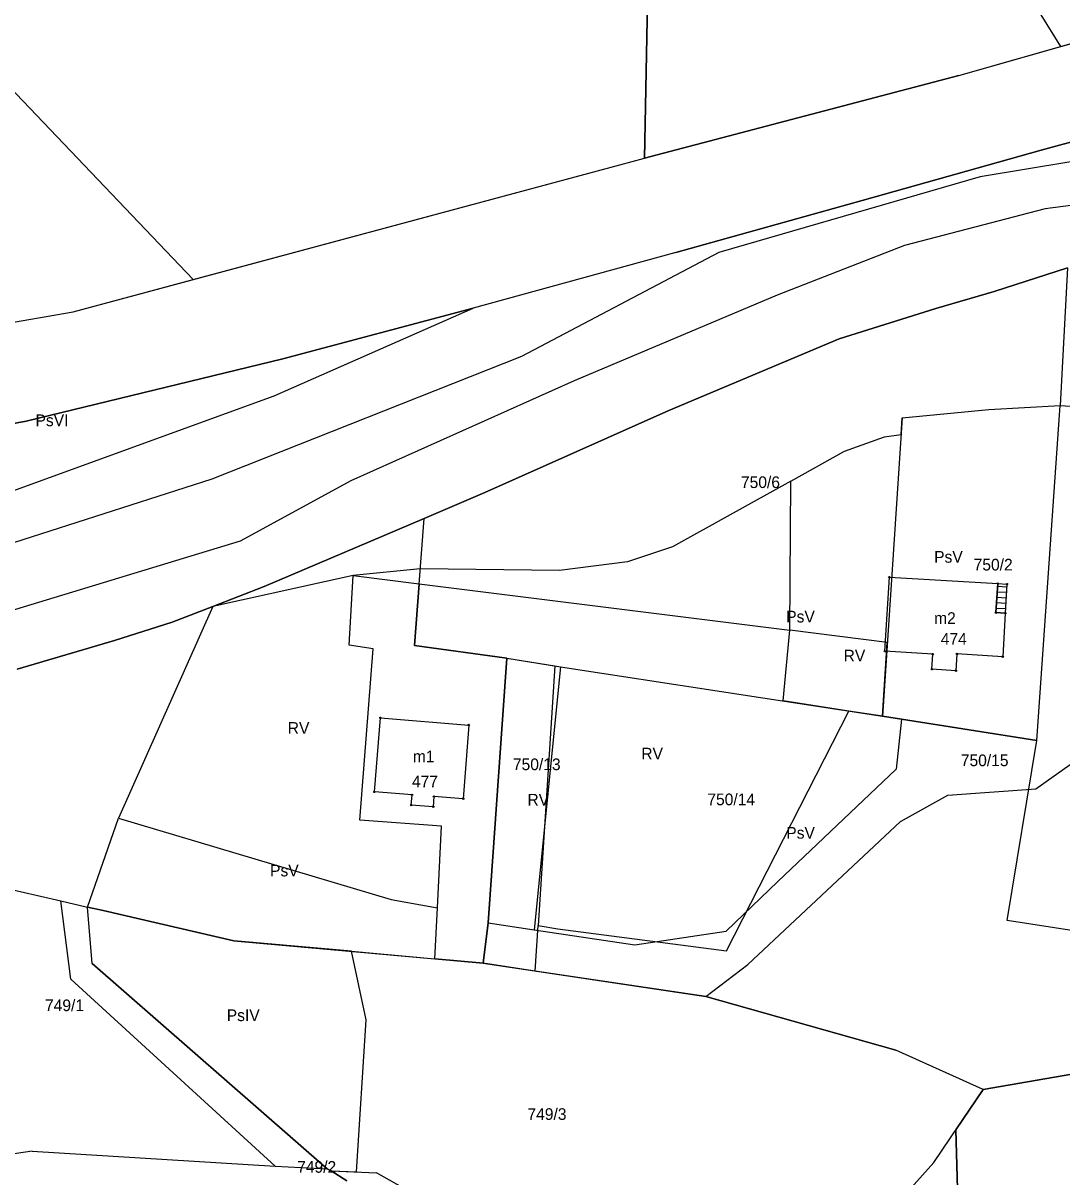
# Model space of a CAD drawing. Extents: x 7498273 to 7499989, y 5499795 to 5500810.
# Drawn here: x 7498760.3 to 7498893.9, y 5500402.3 to 5500550.6 of the extents above; entities that cross this region are included whole.
import ezdxf

# ---------------------------------------------------------------- set-up
doc = ezdxf.new("R2010")
doc.units = 0
for name, color, linetype in [('209-oznaczenie konturu klasyfikacyjnego', 7, 'Continuous'), ('211-numer działki ewidencyjnej', 7, 'Continuous'), ('217-kontur klasyfikacyjny', 7, 'Continuous'), ('218-kontur użytku gruntowego', 7, 'Continuous'), ('219-działka ewidencyjna', 7, 'Continuous'), ('312-budynek ewidencyjny', 7, 'Continuous'), ('312-oznaczenie budynku ewidencyjnego', 7, 'Continuous'), ('312-oznaczenie budynku ewidencyjnego-Atr117', 7, 'Continuous'), ('352-schody', 7, 'Continuous'), ('Punkt budynku', 7, 'Continuous')]:
    doc.layers.add(name, color=color, linetype=linetype)

# ---------------------------------------------------------------- blocks, each defined once
blk = doc.blocks.new('PUNKTBUD')
blk.add_circle((0, 0), 0.09)

msp = doc.modelspace()

# ---------------------------------------------------------------- linework, layer by layer
at = {"layer": '217-kontur klasyfikacyjny'}
for points in [[(7498680.6, 5500624.12), (7498782.21, 5500517.64)], [(7498840.2, 5500533.22), (7498841.35, 5500591.13)], [(7498893.74, 5500547.57), (7498880.69, 5500568.66)], [(7498893.74, 5500547.57), (7498896.05, 5500548.23)], [(7498880.64, 5500543.86), (7498893.74, 5500547.57)], [(7498840.2, 5500533.22), (7498880.64, 5500543.86)], [(7498782.21, 5500517.64), (7498837.03, 5500532.36)], [(7498837.03, 5500532.36), (7498840.2, 5500533.22)], [(7498894.59, 5500519.13), (7498885.18, 5500516.08)], [(7498766.75, 5500513.49), (7498782.21, 5500517.64)], [(7498885.18, 5500516.08), (7498877.68, 5500513.92)], [(7498737, 5500508.34), (7498766.75, 5500513.49)], [(7498792.59, 5500502.66), (7498818.17, 5500513.96)], [(7498818.17, 5500513.96), (7498793.71, 5500507.42)], [(7498877.68, 5500513.92), (7498865.26, 5500510)], [(7498865.26, 5500510), (7498843.35, 5500500.8)], [(7498793.71, 5500507.42), (7498760.71, 5500499.44)], [(7498754.23, 5500488.74), (7498792.59, 5500502.66)], [(7498843.35, 5500500.8), (7498819.71, 5500490.24)], [(7498873.33, 5500499.87), (7498884.51, 5500500.92)], [(7498884.51, 5500500.92), (7498893.65, 5500501.42)], [(7498890.67, 5500458.39), (7498893.65, 5500501.42)], [(7498893.65, 5500501.42), (7498896.19, 5500501.25)], [(7498760.71, 5500499.44), (7498750.04, 5500497.45)], [(7498873.2, 5500497.69), (7498873.33, 5500499.87)], [(7498865.95, 5500495.57), (7498871.08, 5500497.39)], [(7498871.08, 5500497.39), (7498873.2, 5500497.69)], [(7498859.02, 5500491.72), (7498865.95, 5500495.57)], [(7498859.02, 5500491.72), (7498843.84, 5500483.28)], [(7498858.89, 5500472.55), (7498859.02, 5500491.72)], [(7498819.71, 5500490.24), (7498811.87, 5500486.93)], [(7498811.87, 5500486.93), (7498791.33, 5500478.16)], [(7498843.84, 5500483.28), (7498838.02, 5500481.34)], [(7498811.39, 5500480.45), (7498802.77, 5500479.58)], [(7498829.3, 5500480.21), (7498811.39, 5500480.45)], [(7498838.02, 5500481.34), (7498829.3, 5500480.21)], [(7498802.77, 5500479.58), (7498784.71, 5500475.61)], [(7498802.24, 5500470.64), (7498802.77, 5500479.58)], [(7498802.77, 5500479.58), (7498811.24, 5500478.52)], [(7498811.24, 5500478.52), (7498810.65, 5500470.59)], [(7498811.24, 5500478.52), (7498858.89, 5500472.55)], [(7498791.33, 5500478.16), (7498784.71, 5500475.61)], [(7498784.71, 5500475.61), (7498772.58, 5500448.4)], [(7498784.71, 5500475.61), (7498779.48, 5500473.6)], [(7498779.48, 5500473.6), (7498772.06, 5500471.22)], [(7498858.03, 5500463.46), (7498858.89, 5500472.55)], [(7498871.44, 5500470.98), (7498858.89, 5500472.55)], [(7498772.06, 5500471.22), (7498759.55, 5500467.55)], [(7498805.32, 5500470.14), (7498802.24, 5500470.64)], [(7498803.64, 5500448.13), (7498805.32, 5500470.14)], [(7498810.65, 5500470.59), (7498822.51, 5500468.98)], [(7498870.82, 5500461.5), (7498871.44, 5500470.98)], [(7498822.51, 5500468.98), (7498820.1, 5500434.95)], [(7498822.51, 5500468.98), (7498828.68, 5500467.96)], [(7498828.68, 5500467.96), (7498826.55, 5500434.6)], [(7498850.76, 5500431.35), (7498866.5, 5500462.16)], [(7498866.5, 5500462.16), (7498858.03, 5500463.46)], [(7498870.82, 5500461.5), (7498866.5, 5500462.16)], [(7498873.27, 5500461.11), (7498870.82, 5500461.5)], [(7498890.67, 5500458.39), (7498873.27, 5500461.11)], [(7498886.87, 5500435.24), (7498890.67, 5500458.39)], [(7498768.61, 5500436.97), (7498772.58, 5500448.4)], [(7498772.58, 5500448.4), (7498807.65, 5500437.95)], [(7498814.12, 5500447.36), (7498803.64, 5500448.13)], [(7498813.61, 5500436.89), (7498814.12, 5500447.36)], [(7498769.21, 5500429.73), (7498768.61, 5500436.97)], [(7498768.61, 5500436.97), (7498770.62, 5500436.51)], [(7498807.65, 5500437.95), (7498813.61, 5500436.89)], [(7498770.62, 5500436.51), (7498787.44, 5500432.65)], [(7498813.28, 5500430.3), (7498813.61, 5500436.89)], [(7498820.1, 5500434.95), (7498819.47, 5500429.74)], [(7498826.16, 5500428.75), (7498826.55, 5500434.6)], [(7498826.55, 5500434.6), (7498829.07, 5500434.16)], [(7498829.07, 5500434.16), (7498850.76, 5500431.35)], [(7498924.73, 5500429.39), (7498886.87, 5500435.24)], [(7498787.44, 5500432.65), (7498802.55, 5500431.28)], [(7498802.55, 5500431.28), (7498813.28, 5500430.3)], [(7498804.45, 5500422.49), (7498802.55, 5500431.28)], [(7498799.42, 5500403.32), (7498769.21, 5500429.73)], [(7498819.47, 5500429.74), (7498813.28, 5500430.3)], [(7498826.16, 5500428.75), (7498819.47, 5500429.74)], [(7498848.12, 5500425.49), (7498826.16, 5500428.75)], [(7498872.54, 5500418.56), (7498848.12, 5500425.49)], [(7498803.17, 5500402.92), (7498804.45, 5500422.49)], [(7498883.78, 5500413.51), (7498872.54, 5500418.56)], [(7498883.78, 5500413.51), (7498908.79, 5500417.83)], [(7498880.27, 5500408.33), (7498883.78, 5500413.51)], [(7498881.05, 5500379.45), (7498880.27, 5500408.33)], [(7498799.95, 5500403.05), (7498799.42, 5500403.32)], [(7498801.93, 5500401.77), (7498799.95, 5500403.05)], [(7498799.95, 5500403.05), (7498803.17, 5500402.92)]]:
    msp.add_lwpolyline(points, dxfattribs=at)
at = {"layer": '218-kontur użytku gruntowego'}
for points in [[(7498782.21, 5500517.64), (7498680.6, 5500624.12)], [(7498841.35, 5500591.13), (7498840.2, 5500533.22)], [(7498893.74, 5500547.57), (7498880.69, 5500568.66)], [(7498893.74, 5500547.57), (7498896.05, 5500548.23)], [(7498880.64, 5500543.86), (7498893.74, 5500547.57)], [(7498840.2, 5500533.22), (7498880.64, 5500543.86)], [(7498909.17, 5500539.12), (7498891.23, 5500534.26)], [(7498912.14, 5500535.6), (7498883.39, 5500530.82)], [(7498891.23, 5500534.26), (7498868.22, 5500527.8)], [(7498782.21, 5500517.64), (7498837.03, 5500532.36)], [(7498837.03, 5500532.36), (7498840.2, 5500533.22)], [(7498883.39, 5500530.82), (7498849.77, 5500521.1)], [(7498868.22, 5500527.8), (7498844.23, 5500521.12)], [(7498904.28, 5500528.36), (7498891.73, 5500526.7)], [(7498891.73, 5500526.7), (7498873.65, 5500522.01)], [(7498873.65, 5500522.01), (7498857.28, 5500515.63)], [(7498844.23, 5500521.12), (7498818.17, 5500513.96)], [(7498849.77, 5500521.1), (7498824.42, 5500507.73)], [(7498885.18, 5500516.08), (7498894.59, 5500519.13)], [(7498766.75, 5500513.49), (7498782.21, 5500517.64)], [(7498857.28, 5500515.63), (7498831.19, 5500504.6)], [(7498877.68, 5500513.92), (7498885.18, 5500516.08)], [(7498737, 5500508.34), (7498766.75, 5500513.49)], [(7498792.59, 5500502.66), (7498818.17, 5500513.96)], [(7498818.17, 5500513.96), (7498793.71, 5500507.42)], [(7498865.26, 5500510), (7498877.68, 5500513.92)], [(7498843.35, 5500500.8), (7498865.26, 5500510)], [(7498793.71, 5500507.42), (7498760.71, 5500499.44)], [(7498824.42, 5500507.73), (7498784.58, 5500491.95)], [(7498831.19, 5500504.6), (7498802.46, 5500491.75)], [(7498754.23, 5500488.74), (7498792.59, 5500502.66)], [(7498819.71, 5500490.24), (7498843.35, 5500500.8)], [(7498873.33, 5500499.87), (7498884.51, 5500500.92)], [(7498884.51, 5500500.92), (7498893.65, 5500501.42)], [(7498890.67, 5500458.39), (7498893.65, 5500501.42)], [(7498893.65, 5500501.42), (7498896.19, 5500501.25)], [(7498760.71, 5500499.44), (7498750.04, 5500497.45)], [(7498873.2, 5500497.69), (7498873.33, 5500499.87)], [(7498865.95, 5500495.57), (7498871.08, 5500497.39)], [(7498871.08, 5500497.39), (7498873.2, 5500497.69)], [(7498859.02, 5500491.72), (7498865.95, 5500495.57)], [(7498784.58, 5500491.95), (7498746.37, 5500479.72)], [(7498802.46, 5500491.75), (7498788.23, 5500484.02)], [(7498859.02, 5500491.72), (7498843.84, 5500483.28)], [(7498858.89, 5500472.55), (7498859.02, 5500491.72)], [(7498811.87, 5500486.93), (7498819.71, 5500490.24)], [(7498791.33, 5500478.16), (7498811.87, 5500486.93)], [(7498788.23, 5500484.02), (7498751.99, 5500472.97)], [(7498843.84, 5500483.28), (7498838.02, 5500481.34)], [(7498811.39, 5500480.45), (7498802.77, 5500479.58)], [(7498829.3, 5500480.21), (7498811.39, 5500480.45)], [(7498838.02, 5500481.34), (7498829.3, 5500480.21)], [(7498802.77, 5500479.58), (7498784.71, 5500475.61)], [(7498802.24, 5500470.64), (7498802.77, 5500479.58)], [(7498802.77, 5500479.58), (7498811.24, 5500478.52)], [(7498810.65, 5500470.59), (7498811.24, 5500478.52)], [(7498811.24, 5500478.52), (7498858.89, 5500472.55)], [(7498784.71, 5500475.61), (7498791.33, 5500478.16)], [(7498784.71, 5500475.61), (7498772.58, 5500448.4)], [(7498779.48, 5500473.6), (7498784.71, 5500475.61)], [(7498772.06, 5500471.22), (7498779.48, 5500473.6)], [(7498858.03, 5500463.46), (7498858.89, 5500472.55)], [(7498871.44, 5500470.98), (7498858.89, 5500472.55)], [(7498759.55, 5500467.55), (7498772.06, 5500471.22)], [(7498805.32, 5500470.14), (7498802.24, 5500470.64)], [(7498803.64, 5500448.13), (7498805.32, 5500470.14)], [(7498822.51, 5500468.98), (7498810.65, 5500470.59)], [(7498870.82, 5500461.5), (7498871.44, 5500470.98)], [(7498820.1, 5500434.95), (7498822.51, 5500468.98)], [(7498822.51, 5500468.98), (7498828.68, 5500467.96)], [(7498828.68, 5500467.96), (7498826.55, 5500434.6)], [(7498850.76, 5500431.35), (7498866.5, 5500462.16)], [(7498866.5, 5500462.16), (7498858.03, 5500463.46)], [(7498870.82, 5500461.5), (7498866.5, 5500462.16)], [(7498873.27, 5500461.11), (7498870.82, 5500461.5)], [(7498890.67, 5500458.39), (7498873.27, 5500461.11)], [(7498886.87, 5500435.24), (7498890.67, 5500458.39)], [(7498768.61, 5500436.97), (7498772.58, 5500448.4)], [(7498772.58, 5500448.4), (7498807.65, 5500437.95)], [(7498814.12, 5500447.36), (7498803.64, 5500448.13)], [(7498813.61, 5500436.89), (7498814.12, 5500447.36)], [(7498769.21, 5500429.73), (7498768.61, 5500436.97)], [(7498770.62, 5500436.51), (7498768.61, 5500436.97)], [(7498807.65, 5500437.95), (7498813.61, 5500436.89)], [(7498787.44, 5500432.65), (7498770.62, 5500436.51)], [(7498813.28, 5500430.3), (7498813.61, 5500436.89)], [(7498819.47, 5500429.74), (7498820.1, 5500434.95)], [(7498826.16, 5500428.75), (7498826.55, 5500434.6)], [(7498826.55, 5500434.6), (7498829.07, 5500434.16)], [(7498829.07, 5500434.16), (7498850.76, 5500431.35)], [(7498924.73, 5500429.39), (7498886.87, 5500435.24)], [(7498802.55, 5500431.28), (7498787.44, 5500432.65)], [(7498804.45, 5500422.49), (7498802.55, 5500431.28)], [(7498802.55, 5500431.28), (7498813.28, 5500430.3)], [(7498799.42, 5500403.32), (7498769.21, 5500429.73)], [(7498819.47, 5500429.74), (7498813.28, 5500430.3)], [(7498826.16, 5500428.75), (7498819.47, 5500429.74)], [(7498848.12, 5500425.49), (7498826.16, 5500428.75)], [(7498872.54, 5500418.56), (7498848.12, 5500425.49)], [(7498803.17, 5500402.92), (7498804.45, 5500422.49)], [(7498883.78, 5500413.51), (7498872.54, 5500418.56)], [(7498908.79, 5500417.83), (7498883.78, 5500413.51)], [(7498883.78, 5500413.51), (7498880.27, 5500408.33)], [(7498880.27, 5500408.33), (7498881.05, 5500379.45)], [(7498799.95, 5500403.05), (7498799.42, 5500403.32)], [(7498801.93, 5500401.77), (7498799.95, 5500403.05)], [(7498799.95, 5500403.05), (7498803.17, 5500402.92)]]:
    msp.add_lwpolyline(points, dxfattribs=at)
at = {"layer": '219-działka ewidencyjna'}
for points in [[(7498840.2, 5500533.22), (7498841.35, 5500591.13)], [(7498880.64, 5500543.86), (7498903.35, 5500550.3)], [(7498880.64, 5500543.86), (7498840.2, 5500533.22)], [(7498891.23, 5500534.26), (7498909.17, 5500539.12)], [(7498868.22, 5500527.8), (7498891.23, 5500534.26)], [(7498766.75, 5500513.49), (7498837.03, 5500532.36)], [(7498837.03, 5500532.36), (7498840.2, 5500533.22)], [(7498844.23, 5500521.12), (7498868.22, 5500527.8)], [(7498844.23, 5500521.12), (7498818.17, 5500513.96)], [(7498885.18, 5500516.08), (7498894.59, 5500519.13)], [(7498894.59, 5500519.13), (7498893.65, 5500501.42)], [(7498877.68, 5500513.92), (7498885.18, 5500516.08)], [(7498737, 5500508.34), (7498766.75, 5500513.49)], [(7498792.59, 5500502.66), (7498818.17, 5500513.96)], [(7498793.71, 5500507.42), (7498818.17, 5500513.96)], [(7498877.68, 5500513.92), (7498865.26, 5500510)], [(7498843.35, 5500500.8), (7498865.26, 5500510)], [(7498760.71, 5500499.44), (7498793.71, 5500507.42)], [(7498754.23, 5500488.74), (7498792.59, 5500502.66)], [(7498819.71, 5500490.24), (7498843.35, 5500500.8)], [(7498873.33, 5500499.87), (7498884.51, 5500500.92)], [(7498884.51, 5500500.92), (7498893.65, 5500501.42)], [(7498890.67, 5500458.39), (7498893.65, 5500501.42)], [(7498750.04, 5500497.45), (7498760.71, 5500499.44)], [(7498873.33, 5500499.87), (7498870.82, 5500461.5)], [(7498819.71, 5500490.24), (7498811.87, 5500486.93)], [(7498791.33, 5500478.16), (7498811.87, 5500486.93)], [(7498810.65, 5500470.59), (7498811.87, 5500486.93)], [(7498779.48, 5500473.6), (7498791.33, 5500478.16)], [(7498772.06, 5500471.22), (7498779.48, 5500473.6)], [(7498759.55, 5500467.55), (7498772.06, 5500471.22)], [(7498810.65, 5500470.59), (7498822.51, 5500468.98)], [(7498822.51, 5500468.98), (7498820.1, 5500434.95)], [(7498822.51, 5500468.98), (7498829.44, 5500467.83)], [(7498829.44, 5500467.83), (7498826.05, 5500434.05)], [(7498829.44, 5500467.83), (7498870.82, 5500461.5)], [(7498870.82, 5500461.5), (7498873.27, 5500461.11)], [(7498873.27, 5500461.11), (7498872.56, 5500454.71)], [(7498873.27, 5500461.11), (7498890.67, 5500458.39)], [(7498890.52, 5500452.15), (7498896.27, 5500456.23)], [(7498857.37, 5500440.27), (7498872.56, 5500454.71)], [(7498879.24, 5500451.35), (7498890.52, 5500452.15)], [(7498873.13, 5500447.95), (7498879.24, 5500451.35)], [(7498853.49, 5500429.59), (7498873.13, 5500447.95)], [(7498850.74, 5500433.88), (7498857.37, 5500440.27)], [(7498757.27, 5500439.55), (7498765.19, 5500437.75)], [(7498765.19, 5500437.75), (7498768.61, 5500436.97)], [(7498766.45, 5500427.7), (7498765.19, 5500437.75)], [(7498769.21, 5500429.73), (7498768.61, 5500436.97)], [(7498768.61, 5500436.97), (7498770.62, 5500436.51)], [(7498770.62, 5500436.51), (7498787.44, 5500432.65)], [(7498819.47, 5500429.74), (7498820.1, 5500434.95)], [(7498820.1, 5500434.95), (7498826.05, 5500434.05)], [(7498826.05, 5500434.05), (7498838.97, 5500432.12)], [(7498787.44, 5500432.65), (7498819.47, 5500429.74)], [(7498838.97, 5500432.12), (7498850.74, 5500433.88)], [(7498769.21, 5500429.73), (7498799.42, 5500403.32)], [(7498819.47, 5500429.74), (7498848.12, 5500425.49)], [(7498848.12, 5500425.49), (7498853.49, 5500429.59)], [(7498766.45, 5500427.7), (7498792.74, 5500403.68)], [(7498848.12, 5500425.49), (7498872.54, 5500418.56)], [(7498883.78, 5500413.51), (7498872.54, 5500418.56)], [(7498883.78, 5500413.51), (7498908.79, 5500417.83)], [(7498877.42, 5500404.13), (7498883.78, 5500413.51)], [(7498761.49, 5500405.6), (7498752.79, 5500404.3)], [(7498761.49, 5500405.6), (7498792.74, 5500403.68)], [(7498792.74, 5500403.68), (7498799.42, 5500403.32)], [(7498799.42, 5500403.32), (7498799.95, 5500403.05)], [(7498799.95, 5500403.05), (7498801.93, 5500401.77)], [(7498799.95, 5500403.05), (7498805.77, 5500402.82)], [(7498841.78, 5500382.52), (7498805.77, 5500402.82)], [(7498869.05, 5500394.79), (7498877.42, 5500404.13)]]:
    msp.add_lwpolyline(points, dxfattribs=at)
at = {"layer": '312-budynek ewidencyjny'}
for points in [[(7498871.14, 5500469.85), (7498871.7, 5500479.37)], [(7498871.7, 5500479.37), (7498885.63, 5500478.55)], [(7498885.63, 5500478.55), (7498885.4, 5500474.81)], [(7498885.4, 5500474.81), (7498886.6, 5500474.74)], [(7498886.6, 5500474.74), (7498886.28, 5500469.15)], [(7498877.28, 5500469.48), (7498871.14, 5500469.85)], [(7498877.17, 5500467.53), (7498877.28, 5500469.48)], [(7498880.38, 5500469.5), (7498880.26, 5500467.35)], [(7498886.28, 5500469.15), (7498880.38, 5500469.5)], [(7498880.26, 5500467.35), (7498877.17, 5500467.53)], [(7498805.49, 5500451.77), (7498806.27, 5500461.3)], [(7498806.27, 5500461.3), (7498817.62, 5500460.37)], [(7498817.62, 5500460.37), (7498816.92, 5500450.9)], [(7498810.34, 5500451.38), (7498805.49, 5500451.77)], [(7498810.24, 5500450.08), (7498810.34, 5500451.38)], [(7498813.15, 5500451.18), (7498813.05, 5500449.87)], [(7498816.92, 5500450.9), (7498813.15, 5500451.18)], [(7498813.05, 5500449.87), (7498810.24, 5500450.08)]]:
    msp.add_lwpolyline(points, dxfattribs=at)
at = {"layer": '352-schody'}
msp.add_lwpolyline([(7498885.4, 5500474.81), (7498885.63, 5500478.55), (7498886.82, 5500478.48), (7498886.6, 5500474.74)], close=True, dxfattribs=at)
msp.add_lwpolyline([(7498885.4, 5500474.81), (7498885.63, 5500478.55), (7498886.82, 5500478.48), (7498886.6, 5500474.74)], close=True, dxfattribs=at)
for points in [[(7498885.566, 5500477.502), (7498886.758, 5500477.429)], [(7498885.609, 5500478.201), (7498886.799, 5500478.127)], [(7498885.48, 5500476.105), (7498886.676, 5500476.031)], [(7498885.523, 5500476.803), (7498886.717, 5500476.73)], [(7498885.437, 5500475.406), (7498886.635, 5500475.332)]]:
    msp.add_lwpolyline(points, dxfattribs=at)

# ---------------------------------------------------------------- block references
at = {"layer": 'Punkt budynku'}
for p in [(7498871.7, 5500479.37), (7498885.63, 5500478.55), (7498886.82, 5500478.48), (7498885.4, 5500474.81), (7498886.6, 5500474.74), (7498871.14, 5500469.85), (7498877.28, 5500469.48), (7498880.38, 5500469.5), (7498886.28, 5500469.15), (7498877.17, 5500467.53), (7498880.26, 5500467.35), (7498806.27, 5500461.3), (7498817.62, 5500460.37), (7498805.49, 5500451.77), (7498810.34, 5500451.38), (7498813.15, 5500451.18), (7498816.92, 5500450.9), (7498810.24, 5500450.08), (7498813.05, 5500449.87)]:
    msp.add_blockref('PUNKTBUD', p, dxfattribs=at)

# ---------------------------------------------------------------- texts
at = {"layer": '209-oznaczenie konturu klasyfikacyjnego'}
for s, p in [('PsVI', (7498761.92, 5500498.78)), ('PsV', (7498877.46, 5500481.23)), ('PsV', (7498858.44, 5500473.55)), ('RV', (7498865.82, 5500468.54)), ('RV', (7498794.35, 5500459.24)), ('RV', (7498839.81, 5500455.94)), ('RV', (7498825.17, 5500450.02)), ('PsV', (7498858.45, 5500445.76)), ('PsV', (7498792.08, 5500440.91)), ('PsIV', (7498786.51, 5500422.31))]:
    msp.add_text(s, height=1.5, dxfattribs=at).set_placement(p)
at = {"layer": '211-numer działki ewidencyjnej'}
for s, p in [('750/6', (7498852.62, 5500490.83)), ('750/2', (7498882.54, 5500480.23)), ('750/15', (7498880.89, 5500455.08)), ('750/13', (7498823.3, 5500454.57)), ('750/14', (7498848.3, 5500450.06)), ('749/1', (7498763.14, 5500423.59)), ('749/3', (7498825.17, 5500409.61)), ('749/2', (7498795.56, 5500402.82))]:
    msp.add_text(s, height=1.5, dxfattribs=at).set_placement(p)
at = {"layer": '312-oznaczenie budynku ewidencyjnego'}
for s, p in [('474', (7498878.31, 5500470.68)), ('477', (7498810.32, 5500452.37))]:
    msp.add_text(s, height=1.5, dxfattribs=at).set_placement(p)
at = {"layer": '312-oznaczenie budynku ewidencyjnego-Atr117'}
for s, p in [('m2', (7498877.456, 5500473.36)), ('m1', (7498810.435, 5500455.59))]:
    msp.add_text(s, height=1.5, dxfattribs=at).set_placement(p)

doc.saveas('drawing.dxf')
